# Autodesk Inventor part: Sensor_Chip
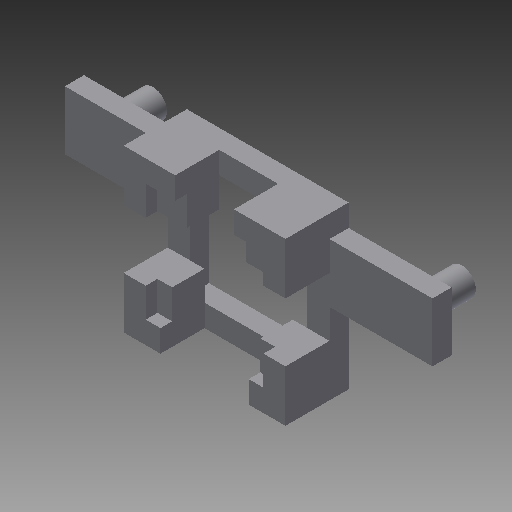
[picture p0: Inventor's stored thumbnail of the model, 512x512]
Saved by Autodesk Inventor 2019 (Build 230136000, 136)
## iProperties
Created: 2015-10
Part Number: Sensor_Chip
Material: Generic
Document SubType Name: Modeling
Designer: Chris
Density: 1 g/cm^3
Appearance: Default
Author: Chris
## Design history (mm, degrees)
sketch "Sketch1"
  geometry: L1 (-5.5, 5.5)-(5.5, 5.5); L2 (5.5, 5.5)-(5.5, 4); L3 (5.5, -5.5)-(-5.5, -5.5); L4 (-5.5, -5.5)-(-5.5, 0); L5 (-12.5, 4)-(-5.5, 4); L6 (12.5, 4)-(12.5, 0); L7 (12.5, 0)-(5.5, 0); L8 (-12.5, 0)-(-12.5, 4); L9 (-5.5, 4)-(5.5, 4); L10 (5.5, 4)-(12.5, 4); L11 (-5.5, 0)-(-12.5, 0); L12 (5.5, 0)-(-5.5, 0); L13 (4, 4)-(-4, 4); L14 (-4, 4)-(-4, -4); L15 (-4, -4)-(4, -4); L16 (4, -4)-(4, 4); L17 (-5.5, 4)-(-5.5, 5.5); L18 (-5.5, 0)-(-5.5, 4); L19 (5.5, 4)-(5.5, 0); L20 (5.5, 0)-(5.5, -5.5); 5 further points
  constraints: 40 end point, 22 parallel, 7 perpendicular, 4 horizontal, 4 midpoint, 2 equal length, 2 horizontal alignment, 2 vertical alignment, 1 point on line
  dimensions: "d2" = 4 distance of L6.start L6.end; "d4" = 7 distance of L5.start L5.end; "d5" = 1.5 distance between parallel lines of L1 L13; "d6" = 8 distance of L14.end L15.end; "d7" = 1.5 distance between parallel lines of L3 L15; "d8" = 1.5 distance between parallel lines of L20 L16
extrude "BottomPlane" new body sketch "Sketch1" distance "d9" = 1.3; taper "d10" = 0 deg
sketch "Sketch2"
  geometry: L1 (-5.5, 5.5)-(-2, 5.5); L2 (-2, 5.5)-(-2, 2); L3 (-2, 2)-(-5.5, 2); L4 (-5.5, 2)-(-5.5, 5.5); L5 (5.5, 5.5)-(2, 5.5); L6 (2, 5.5)-(2, 2); L7 (2, 2)-(5.5, 2); L8 (5.5, 2)-(5.5, 5.5); L9 (-5.5, -5.5)-(-3, -5.5); L10 (-3, -5.5)-(-3, -2); L11 (-3, -2)-(-5.5, -2); L12 (-5.5, -2)-(-5.5, -5.5); L13 (5.5, -5.5)-(3, -5.5); L14 (3, -5.5)-(3, -2); L15 (3, -2)-(5.5, -2); L16 (5.5, -2)-(5.5, -5.5); 1 further point
  constraints: 32 end point, 8 parallel, 4 equal length, 4 horizontal, 4 perpendicular, 1 collinear, 1 point on line
  dimensions: "d12" = 3.5 distance of L11.end L9.start; "d13" = 2.5 distance of L10.end L11.end
extrude "UpperWalls" join sketch "Sketch2" distance "d14" = 3; taper "d15" = 0 deg
sketch "Sketch3"
  geometry: L1 (-4, 4)-(4, 4); L2 (4, 4)-(4, -4); L3 (4, -4)-(-4, -4); L4 (-4, -4)-(-4, 4); L5 (5.5, 5.5)-(2, 5.5) reference; L6 (5.5, 2)-(5.5, 5.5) reference; L7 (3, -5.5)-(5.5, -5.5) reference; 2 further points
  constraints: 8 end point, 2 parallel, 1 horizontal, 1 midpoint, 1 perpendicular, 1 vertical alignment
  dimensions: "d16" = 1.5 distance between parallel lines of L5 L1; "d17" = 1.5 distance between parallel lines of L6 L2; "d18" = 1.5 distance between parallel lines of L7 L3
extrude "SensorHollow" cut sketch "Sketch3" distance "d19" = 0.8; taper "d20" = 0 deg
sketch "Sketch4"
  geometry: L1 (12.5, 0)-(12.5, 4) reference; L2 (0, -7.7)-(0, 7.7) reference; C1 r 0.95 at (10.5, 2); C2 r 0.95 at (-10.5, 2); 2 further points
  constraints: 2 centre point, 2 horizontal alignment, 1 midpoint, 1 other
  dimensions: "d21" = 1.9 diameter of C1; "d23" = 21 distance of C2.centre C1.centre
extrude "LowerPillar" join sketch "Sketch4" distance "d24" = 2.7; taper "d25" = 0 deg
body "Solid1"
